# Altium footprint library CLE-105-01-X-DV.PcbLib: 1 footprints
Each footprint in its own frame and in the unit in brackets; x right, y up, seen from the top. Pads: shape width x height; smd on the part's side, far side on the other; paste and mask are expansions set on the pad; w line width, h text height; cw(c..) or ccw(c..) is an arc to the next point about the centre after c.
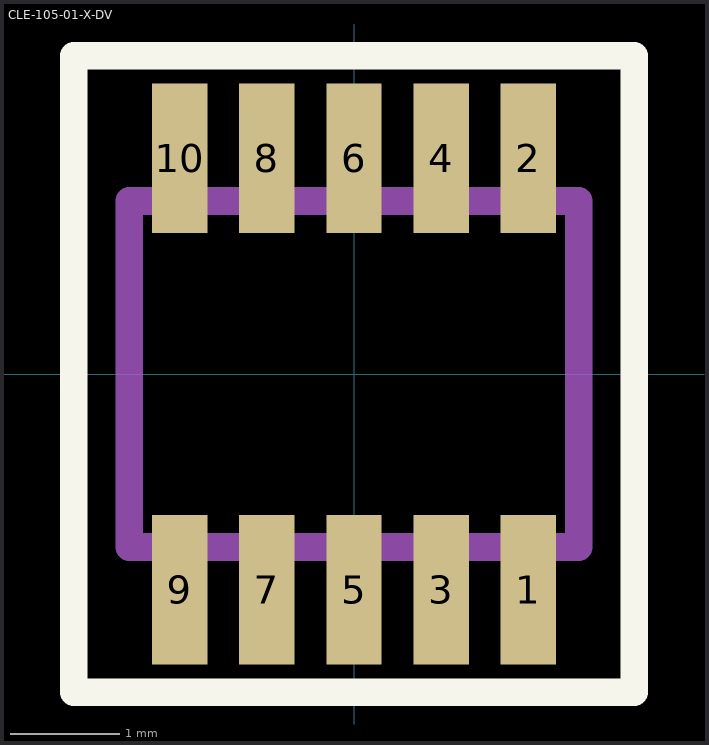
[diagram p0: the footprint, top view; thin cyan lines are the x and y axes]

## CLE-105-01-X-DV [mil]
pads (10):
  rect 20x54 smd mask+2: 1(63,-78) 2(63,78) 3(31.5,-78) 4(31.5,78) 5(0,-78) 6(0,78) 7(-31.5,-78) 8(-31.5,78) 9(-63,-78) 10(-63,78)
Top Overlay:
  lines w10: -101.25,-115 101.25,-115 101.25,115 -101.25,115 -101.25,-115
Mechanical 1:
  lines w10: -81.25,-62.5 81.25,-62.5 81.25,62.5 -81.25,62.5 -81.25,-62.5
  text "J1" at -17.3,-17.72 h29.53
